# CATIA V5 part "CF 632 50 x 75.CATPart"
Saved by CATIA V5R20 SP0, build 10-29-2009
Part number: CF 632 50 x 75
Definition: NONE
Nomenclature: CF 632 50 x 75
Source: Unknown
Description: CF 632 50 x 75
Bounding box of the stored display mesh (mm): x -13 to 62, y -39.5 to 39.5, z -39.5 to 39.5
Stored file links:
  C:\Users\Utente\Desktop\IO LAVORO\3D X SITO CF\X SITO\CF 632\CF 632 50 x 75.CATPart
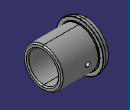
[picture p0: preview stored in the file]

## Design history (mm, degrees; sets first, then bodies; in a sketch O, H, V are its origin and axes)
Body1 "CF 632 50 x 75" (main body)
  Solid1: solid without history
